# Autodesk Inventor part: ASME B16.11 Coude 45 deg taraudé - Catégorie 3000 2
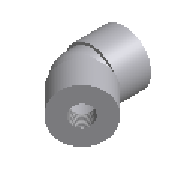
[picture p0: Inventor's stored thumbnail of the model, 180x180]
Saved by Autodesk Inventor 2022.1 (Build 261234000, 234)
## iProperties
Created: 2021-02
Part Number: ASME B16.11 Coude 45 deg taraudé - Catégorie 3000 2
Material: Acier
Description: Coude 45° taraudé - Forgé - Catégorie 3000
Document SubType Name: Modeling
Standard: ASME B16.11
Designer: Fabian
Standard Revision: 2011
Standards Organization: ANSI
Language: fr-FR
Size Designation: 2
Categories: <MemberInstance><Categories><Category DisplayName="Tubes et tuyaux" InternalName="4347fa0f-2144-441d-94cd-e3e15c92b736" Mnemonic="TUBEANDPIPE"><CategoryParamete
Density: 1 g/cm^3
Appearance: Plaque
IsCustomPart: 0
L2: 0,757 po
NAME: PIPING: ASME B16.11 45 Deg Elbow Threaded - Class 3000
DATA: <meta><inlinegroups number="0" deflen="0"></inlinegroups><connections number="2"></connections><angles><a>2.35619449019234</a></angles></meta>
Author: Fabian
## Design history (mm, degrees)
sketch "Sketch1"
  geometry: L1 (0, 0)-(0, 43.688); L2 (0, 43.688)-(-30.892, 74.58); L3 (-30.892, 74.58)-(-57.644, 47.828); L4 (-57.644, 47.828)-(-26.752, 16.936); L5 (0, 43.688)-(-26.752, 16.936); L6 (0, 43.688)-(-37.833, 43.688); L7 (-37.833, 43.688)-(-37.833, 0); L8 (0, 0)-(-37.833, 0); L9 (-37.833, 28.017)-(0, 43.688); L10 (-37.833, 28.017)-(0, 28.017); L11 (-37.833, 28.017)-(-11.081, 54.769); L12 (-30.892, 74.58)-(-10.896, 94.576); L13 (-10.896, 94.576)-(2.267, 80.565); L14 (2.267, 80.565)-(4.4, 82.698); L15 (4.4, 82.698)-(21.705, 65.393); L16 (0, 43.688)-(21.705, 65.393); L17 (2.267, 80.565)-(-17.305, 60.993); L18 (0, 0)-(28.279, 0); L19 (28.279, 0)-(27.679, 19.215); L20 (27.679, 19.215)-(30.696, 19.215); L21 (30.696, 19.215)-(30.696, 43.688); L22 (0, 43.688)-(30.696, 43.688); L23 (27.679, 19.215)-(0, 19.215)
  constraints: 46 end point, 14 perpendicular, 7 point on line, 3 parallel, 1 vertical
  dimensions: "d0" = 43.688 distance of L3.end L4.end (= C1); "d1" = 43.688 distance of L6.end L7.end (= C1); "d2" = 135 deg angle of L1 L2; "d3" = 75.6666 diameter of L3.end L2 (= 0.9 x H); "d4" = 75.6666 diameter of L7.end L1 (= 0.9 x H); "d5" = 56.55818 diameter of L12.end L2 (= MD); "d6" = 61.3918 diameter of L14.end L2 (= 0.9 x H - 2 x G); "d7" = 19.2151 distance of L2.end L17.end (= L2); "d8" = 1.78991 deg angle of L2 L13; "d9" = 56.55818 diameter of L18.end L1 (= MD); "d10" = 61.3918 diameter of L20.end L1 (= 0.9 x H - 2 x G); "d11" = 19.2151 distance of L1.start L23.end (= L2); "d12" = 1.78991 deg angle of L1 L19
workplane "Work Plane1"
workplane "Work Plane2"
sketch "Sketch2"
  geometry: L1 (0, 0)-(37.833, 0) reference; C1 r 37.833 at (0, 0); C2 r 42.037 at (0, 0)
  constraints: 2 centre point, 2 coincident
  dimensions: "d15" = 75.6666 diameter of C1 (= 0.9 x H); "d18" = 84.074 diameter of C2 (= H)
extrude "Extrude1" new body sketch "Sketch2" distance "d16" = 43.688 (= C1); taper "d17" = 0 deg
extrude "Extrude2" join sketch "Sketch2" distance "d19" = 34.07664 (= 0.78 x C1); taper "d20" = 0 deg
sketch "Sketch3"
  geometry: L1 (0, 0)-(37.833, 0) reference; C1 r 37.833 at (0, 0); C2 r 42.037 at (0, 0)
  constraints: 2 centre point, 2 coincident
  dimensions: "d22" = 75.6666 diameter of C1 (= 0.9 x H); "d25" = 84.074 diameter of C2 (= H)
extrude "Extrude3" join sketch "Sketch3" distance "d23" = 43.688 (= C1); taper "d24" = 0 deg
extrude "Extrude4" join sketch "Sketch3" distance "d26" = 34.07664 (= 0.78 x C1); taper "d27" = 0 deg
revolve "Revolve1" stored, may be unused: angle "d21" = 90 deg
revolve "Revolve2" stored, may be unused: angle "d28" = 90 deg
sketch "Sketch4"
  geometry: L1 (0, 37.833)-(0, 30.696) reference; L2 (0, -30.696)-(0, -37.833) reference; L3 (0, 30.696)-(0, -30.696); L4 (0, -30.696)-(0, -37.833); L5 (0, 30.696)-(0, 37.833); A1 r 30.696 centre (0, 0) between (0, 30.696) and (0, -30.696) reference; A2 r 37.833 centre (0, 0) between (0, 37.833) and (0, -37.833) reference; A3 r 37.833 centre (0, 0) between (0, 37.833) and (0, -37.833); A4 r 30.696 centre (0, 0) between (0, 30.696) and (0, -30.696)
  constraints: 6 end point, 4 point on circle, 3 collinear, 2 centre point, 2 concentric, 1 coincident, 1 midpoint, 1 point on line
  dimensions: "d29" = 37.8333 radius of A3 (= 0.45 x H); "d30" = 30.6959 radius of A4 (= 0.45 x H - G)
revolve "Revolve3" sketch "Sketch4" stored, may be unused: angle "d31" = 45 deg
workaxis "Work Axis1"
workpoint "Work Point1"
workpoint "Work Point2"
workaxis "Work Axis2"
workpoint "Work Point3"
workpoint "Work Point4"
body "Solid1"
feature "Filetage1" dims "d32" = 25.4, "d33" = 0
feature "Filetage2" dims "d34" = 25.4, "d35" = 0
other parameters: "C1" = 43.688 [user parameter; used in 6 equation terms], "H" = 84.074 [user parameter; used in 10 equation terms], "G" = 7.1374 [user parameter; used in 3 equation terms], "L2" = 19.2151 [user parameter; used in 2 equation terms], "MD" = 56.55818 [user parameter; used in 2 equation terms], "d13" = 90 deg, "d14" = 90 deg, "A" = 63.5 [user parameter]
